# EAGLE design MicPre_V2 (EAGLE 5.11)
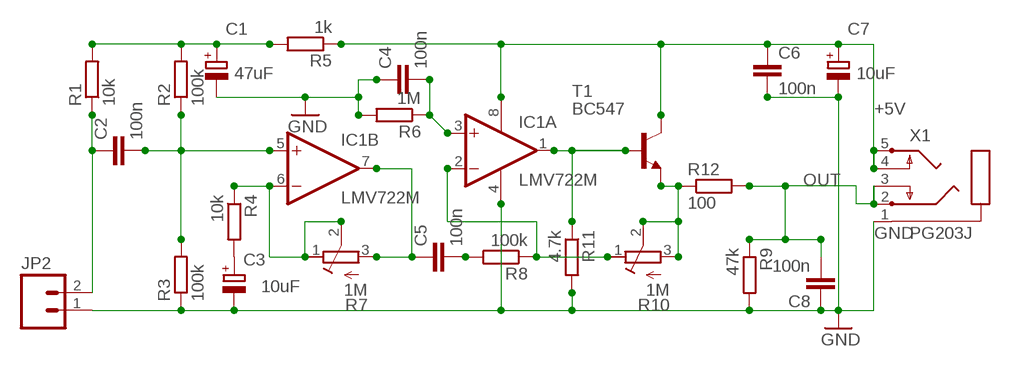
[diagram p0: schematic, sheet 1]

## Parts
C1  47uF  CPOL-EUCT6032  [CT6032]
C2  100n  C-EUC0805K  [C0805K]
C3  10uF  CPOL-EUCT6032  [CT6032]
C4  100n  C-EUC0805K  [C0805K]
C5  100n  C-EUC0805K  [C0805K]
C6  100n  C-EUC0805K  [C0805K]
C7  10uF  CPOL-EUCT6032  [CT6032]
C8  100n  C-EUC0805K  [C0805K]
IC1  LMV722M  LMV358M  [SO08]
JP2  M02PTH  [1X02]
R1  10k  R-EU_M0805  [M0805]
R2  100k  R-EU_M0805  [M0805]
R3  100k  R-EU_M0805  [M0805]
R4  10k  R-EU_M0805  [M0805]
R5  1k  R-EU_M0805  [M0805]
R6  1M  R-EU_M0805  [M0805]
R7  1M  R-TRIMMT93YA  [RTRIMT93YA]
R8  100k  R-EU_M0805  [M0805]
R9  47k  R-EU_M0805  [M0805]
R10  1M  R-TRIMMT93YA  [RTRIMT93YA]
R11  4.7k  R-EU_M0805  [M0805]
R12  100  R-EU_M0805  [M0805]
T1  BC547  [TO92]
X1  PG203J  [PG203J]

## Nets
+5V: C6.1 C7.+ IC1.8(P:V+) R5.1 T1.3(C) X1.4 X1.5
GND: C1.- C3.- C4.1 C6.2 C7.- C8.1 IC1.4(P:V-) JP2.1 R3.1 R6.2 R9.2 R11.2 X1.1
MIC+: C2.1 JP2.2 R1.1
N$1: C1.+ R1.2 R2.2 R5.2
N$2: C3.+ R4.2
N$3: IC1.2(A:-IN) R8.1 R10.1(A)
N$5: IC1.6(B:-IN) R4.1 R7.1(A) R7.2(S)
N$6: C4.2 IC1.3(A:+IN) R6.1
N$7: C5.2 R8.2
N$9: R10.2(S) R10.3(E) R12.1 T1.1(E)
N$10: C2.2 IC1.5(B:+IN) R2.1 R3.2
N$11: C5.1 IC1.7(B:OUT) R7.3(E)
N$12: IC1.1(A:OUT) R11.1 T1.2(B)
OUT: C8.2 R9.1 R12.2 X1.2 X1.3

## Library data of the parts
C1 C3 C7 = rcl:CPOL-EU: POLARIZED CAPACITOR, European symbol
C2 C4-C6 C8 = rcl:C-EU: CAPACITOR, European symbol
IC1 = linear:LMV358?*: Dual General Purpose, Low Voltage, Rail-to-Rail Output Operational Amplifiers Source: http://www.national.com/mpf/LM/LMV321.html http://www.national.com/dt/lmv_qual.pdf
JP2 = SparkFun:M02: Header 2
R1-R6 R8 R9 R11 R12 = rcl:R-EU_: RESISTOR, European symbol
R7 R10 = rcl:R-TRIMM: Trimm resistor
T1 = transistor:BC547: NPN TRANSISTOR
X1 = con-hirschmann:PG203J: MIC/HEADPHONE JACK KS-S stereo microphone/headphone jack PG203JN (Schukat)

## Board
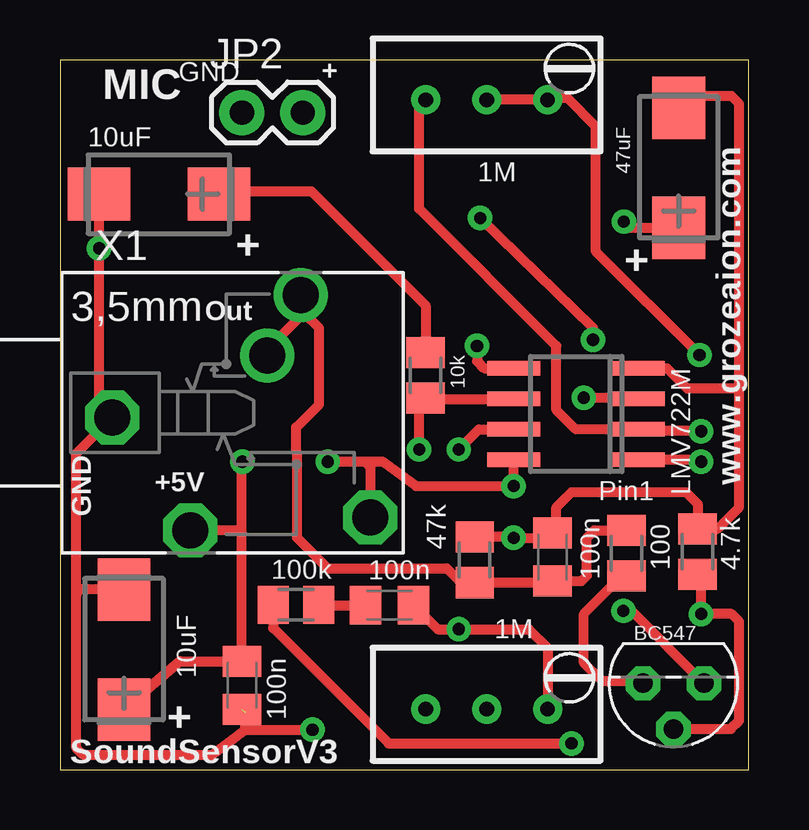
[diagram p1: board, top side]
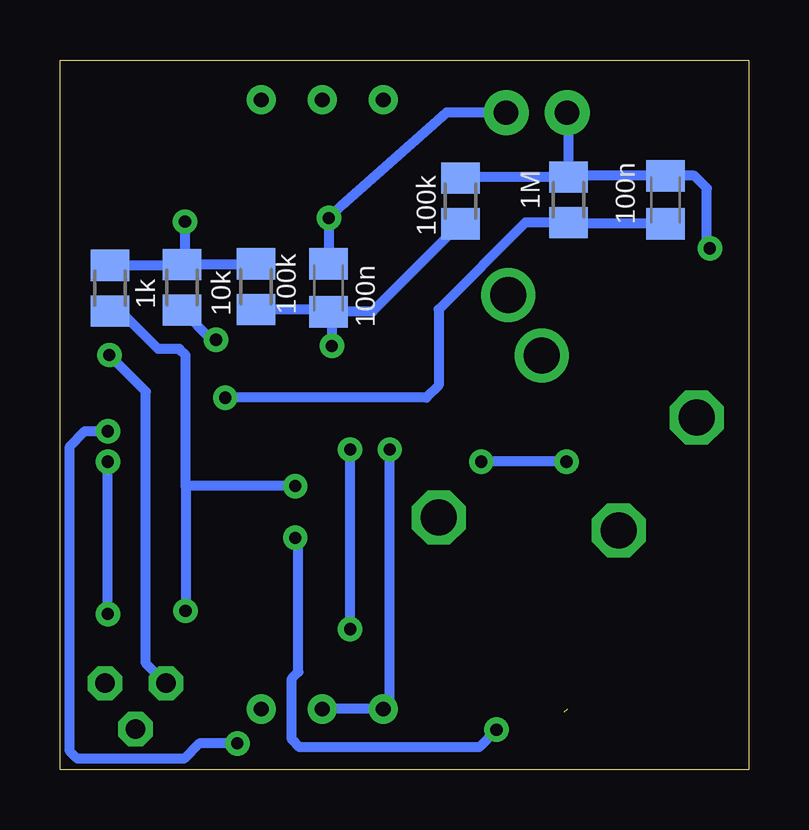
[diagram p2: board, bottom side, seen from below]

Size 28.7 x 29.6 mm. Coordinates in mm from the lower left corner, seen from the top.
Outline: 0,0 28.7,0 28.7,29.6 0,29.6 0,0
Copper layers (1*16): Top 0.035mm / dielectric 1.5mm / Bottom 0.035mm
Design rules "SparkFun": minimum track width 8mil, minimum drill 20mil, track to track 8mil, track to pad 8mil, pad to pad 8mil, via to via 8mil, smd to smd 8mil, copper to edge 10mil, drill to drill 8mil, minimum pad ring 12mil, minimum via ring 10mil, stop-mask expansion 4mil, vias tented up to drill 25mil, thermal gap 10mil

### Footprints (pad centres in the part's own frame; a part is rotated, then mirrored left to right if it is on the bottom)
CT6032 = smd 2.6 x 2.2: + -2.5,0; - 2.5,0
C0805K = smd 1.3 x 1.6: 1 -1,0; 2 1,0
SO08 = smd 0.6 x 2.2: 1 -1.905,-2.6; 2 -0.635,-2.6; 3 0.635,-2.6; 4 1.905,-2.6; 5 1.905,2.6; 6 0.635,2.6; 7 -0.635,2.6; 8 -1.905,2.6
1X02 = drill 1.016 pad 1.88 round: 1 0,0; 2 2.54,0
M0805 = smd 1.3 x 1.6: 1 -0.95,0; 2 0.95,0
RTRIMT93YA = drill 0.61 round: 1 0,-2.54; 2 0,0; 3 0,2.54
TO92 = drill 0.813 octagon: 1 1.27,0; 2 0,1.905; 3 -1.27,0
PG203J = drill 1.499 octagon: 1 -5.004,-0.203; 4 5.74,-4.369; 5 -1.753,-4.902 | drill 1.499 round: 2 2.845,4.902; 3 1.448,2.388

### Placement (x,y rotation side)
C1  25.78,25.11 90 top
C2  17.52,20.1 270 bottom
C3  4.13,24.01 180 top
C4  3.48,23.77 270 bottom
C5  13.73,6.87 180 top
C6  7.58,3.53 270 top
C7  2.66,5.02 90 top
C8  20.52,8.88 270 top
IC1  21.51,14.84 90 top
JP2  7.58,27.4 0 top
R1  23.62,20.12 90 bottom
R2  20.54,20.15 90 bottom
R3  12.02,23.72 270 bottom
R4  15.24,16.46 90 top
R5  26.63,20.09 90 bottom
R6  7.51,23.77 90 bottom
R7  17.78,2.54 270 top
R8  9.83,6.88 0 top
R9  17.28,8.76 90 top
R10  17.78,27.94 270 top
R11  26.56,9.1 90 top
R12  23.61,9.03 90 top
T1  25.56,3.61 180 top
X1  7.19,14.89 0 top

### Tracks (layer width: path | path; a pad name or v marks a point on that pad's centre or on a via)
+5V  (via drill 0.51)
  Top 0.406: v23.47,6.63 23.81,6.63 T1.3 | 7.58,9.84 C6.1 4.99,4.53 C7.+ | 7.58,9.84 7.58,12.83 v7.6,12.85 | 18.83,12.85 IC1.8 v18.91,11.84 v18.9,11.84 14.84,11.84 13.44,12.85 12.7,12.85 | v11.15,12.85 12.7,12.85 | X1.5 7.43,9.99 7.58,9.84 | X1.4 12.93,12.63 12.7,12.85
  Bottom 0.406: 23.47,11.84 v23.47,6.63 | 23.47,11.84 23.47,17.3 23.73,17.55 24.62,17.55 26.14,19.07 26.57,19.07 R5.1 | v18.9,11.84 23.47,11.84 | v7.6,12.85 v11.15,12.85
GND  (via drill 0.51)  (1 unrouted)
  Top 0.406: 28.3,15.9 28.3,10.95 27.4,10.05 R11.2 26.56,11.1 26.08,11.58 21.32,11.58 20.68,10.95 20.68,10.04 C8.1 | 28.3,15.9 28.3,27.77 27.98,28.09 26.26,28.09 C1.- | C8.1 20.35,9.71 | C8.1 20.32,9.68 v18.9,9.68 18.87,9.71 R9.2 | IC1.4 25.3,16.74 26.14,15.9 28.3,15.9 | 0.68,7.3 0.68,13.19 X1.1 1.63,15.24 v1.63,21.74 C3.- | 0.68,7.3 0.78,7.52 C7.- | 0.68,7.3 0.68,0.91 0.95,0.64 6.35,0.64 7.71,1.68 | 7.71,1.68 v10.52,1.68 | 7.71,1.68 7.71,2.4
  Bottom 0.406: R6.2 7.51,27.34 JP2.1 | R6.2 7.46,24.77 C4.1 2.27,24.77 1.76,24.25 1.76,21.87 v1.63,21.74 | R6.2 11.97,24.72 R3.1 | v18.9,9.68 18.77,9.55 18.77,4.08 19.05,3.81 19.05,1.27 18.73,0.95 11.24,0.95 v10.52,1.68
MIC+  (via drill 0.51)
  Top 0.406: v22.2,17.93 22.2,18.44 v17.5,23.01
  Bottom 0.406: JP2.2 12.61,27.4 17,23.52 v17.5,23.01 17.5,21.12 C2.1 | 23.32,19.04 23.32,19.17 R1.1 22.38,17.93 v22.2,17.93
N$1  (via drill 0.51)
  Top 0.406: C1.+ 23.75,22.61 v23.5,22.86
  Bottom 0.406: R2.2 20.56,21.07 R1.2 | R5.2 23.66,21.04 R1.2 | v23.5,22.86 23.5,21.2 R1.2
N$2
  Top 0.406: R4.2 15.24,19.37 10.48,24.13 6.75,24.13 C3.+
N$3  (via drill 0.51)
  Top 0.406: R8.1 8.88,5.92 13.7,1.1 v21.32,1.1 | v26.71,14.12 24.19,14.12 IC1.2 21.49,14.2 20.68,15.01 20.68,17.68 14.96,23.39 14.96,27.53 R10.1
  Bottom 0.406: v21.32,1.1 22.9,1.1 23.54,0.47 27.98,0.47 28.3,0.79 28.3,13.49 27.66,14.12 v26.71,14.12
N$5  (via drill 0.51)
  Top 0.406: IC1.6 15.27,15.47 R4.1 14.96,15.23 v14.96,13.36
  Bottom 0.406: R7.2 R7.1 14.96,2.81 v14.96,13.36
N$6  (via drill 0.51)
  Top 0.406: v21.82,15.52 24.06,15.52 IC1.3
  Bottom 0.406: C4.2 7.46,22.77 R6.1 9.32,22.82 12.93,19.2 12.93,16.03 13.44,15.52 v21.82,15.52
N$7
  Top 0.406: C5.2 10.8,6.87 R8.2
N$9  (via drill 0.51)
  Top 0.406: R12.1 23.41,8.08 21.82,6.5 21.82,4.47 22.59,3.71 24.19,3.71 T1.1 | v26.65,17.3 22.33,21.61 22.33,26.82 21.15,28 R10.3 R10.2
  Bottom 0.406: T1.1 25.12,4.44 25.12,15.77 v26.65,17.3
N$10  (via drill 0.51)
  Top 0.406: IC1.5 17.68,16.74 17.38,17.04 v17.38,17.68
  Bottom 0.406: R2.1 17.62,19.2 C2.2 | C2.2 15.69,19.1 R3.2 | C2.2 17.63,18.99 | v17.38,17.68 17.38,18.96 C2.2
N$11  (via drill 0.51)
  Top 0.406: C5.1 15.73,5.87 v16.62,5.87 19.53,5.87 20.32,5.08 R7.3 | IC1.7 17.46,14.2 v16.62,13.36
  Bottom 0.406: v16.62,5.87 v16.62,13.36
N$12  (via drill 0.51)
  Top 0.406: IC1.1 26.63,12.93 v26.71,12.85 | R11.1 26.71,8 v26.71,6.5 27.98,6.5 28.3,6.18 28.3,2.06 27.95,1.71 T1.2
  Bottom 0.406: v26.71,6.5 v26.71,12.85
OUT
  Top 0.406: R12.2 23.6,9.99 22.27,9.99 21.95,9.68 21.95,8.09 21.74,7.88 C8.2 20.45,7.81 R9.1 16.71,7.81 16.11,8.41 11.15,8.41 9.88,9.68 9.88,13.23 9.84,13.28 9.84,14.29 10.79,15.24 10.79,18.41 10.16,19.05 | X1.2 10.03,19.18 10.16,19.05 | X1.3 8.63,17.52 10.16,19.05

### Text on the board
tPlace: GND | + | MIC | + | + | Out | +5V | www.grozeaion.com | GND | Pin1 | + | SoundSensorV3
